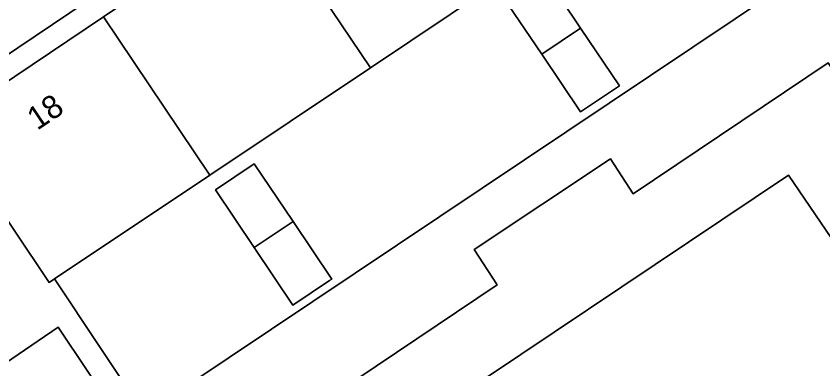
# Model space of a CAD drawing. Extents: x 158793 to 159888, y 384317 to 385256.
# Drawn here: x 159221.85 to 159256.79, y 384582.61 to 384597.87 of the extents above; entities that cross this region are included whole.
import ezdxf

# ---------------------------------------------------------------- set-up
doc = ezdxf.new("R2010")
doc.units = 0
for name, color, linetype in [('IMGEO_Erf', 7, 'Continuous'), ('IMGEO_Groenvoorziening', 7, 'Continuous'), ('IMGEO_Pand', 7, 'Continuous'), ('IMGEO_Pand_nummerreeks', 7, 'Continuous'), ('IMGEO_Rijbaan_lokaal_open', 7, 'Continuous'), ('IMGEO_Voetpad_gesloten', 7, 'Continuous'), ('IMGEO_Voetpad_open', 7, 'Continuous')]:
    doc.layers.add(name, color=color, linetype=linetype)

msp = doc.modelspace()

# ---------------------------------------------------------------- linework, layer by layer
at = {"layer": 'IMGEO_Erf'}
for points in [[(159253.972, 384600.287), (159250.947, 384604.835), (159244.149, 384600.292), (159237.191, 384595.643), (159230.234, 384590.995), (159223.505, 384586.498), (159227.4, 384580.648), (159254.824, 384599.006)], [(159242.935, 384598.725), (159244.619, 384599.858), (159246.296, 384597.36), (159247.98, 384594.851), (159246.292, 384593.732), (159244.614, 384596.228)], [(159233.84, 384588.989), (159235.516, 384586.495), (159235.426, 384586.435), (159233.833, 384585.363), (159232.157, 384587.857), (159230.48, 384590.351), (159232.164, 384591.483)]]:
    msp.add_lwpolyline(points, close=True, dxfattribs=at)
at = {"layer": 'IMGEO_Groenvoorziening'}
for points in [[(159245.073, 384674.375), (159284.084, 384616.156), (159275.927, 384610.681), (159273.311, 384614.477), (159265.419, 384609.219), (159264.866, 384609.954), (159259.381, 384606.275), (159260.51, 384604.607), (159254.969, 384600.946), (159255.845, 384599.623), (159254.824, 384599.006), (159227.4, 384580.648), (159223.505, 384586.498), (159223.273, 384586.343), (159218.681, 384593.177), (159217.583, 384592.512), (159220.423, 384588.255), (159209.629, 384581), (159206.819, 384585.213), (159203.401, 384582.912), (159198.891, 384579.876)], [(159242.691, 384586.237), (159241.692, 384587.769), (159247.59, 384591.694), (159248.575, 384590.183), (159257.026, 384595.85), (159264.913, 384583.752), (159277.399, 384592.138), (159286.257, 384578.984), (159286.133, 384578.901), (159294.892, 384565.894), (159262.678, 384544.258), (159259.822, 384548.509), (159259.697, 384548.426), (159257.475, 384546.941), (159253.387, 384544.208), (159252.964, 384543.926), (159252.893, 384543.878), (159259.749, 384533.873), (159262.59, 384535.774), (159262.993, 384535.164), (159312.028, 384567.885), (159313.543, 384565.466)], [(159208.686, 384574.19), (159223.666, 384584.415), (159228.726, 384576.872), (159242.691, 384586.237)]]:
    msp.add_lwpolyline(points, dxfattribs=at)
msp.add_lwpolyline([(159260.665, 384583.121), (159255.299, 384590.989), (159237.929, 384579.369), (159243.268, 384571.401)], close=True, dxfattribs=at)
at = {"layer": 'IMGEO_Pand'}
for points in [[(159239.509, 384607.189), (159232.566, 384602.519), (159237.191, 384595.643), (159244.149, 384600.292)], [(159232.566, 384602.519), (159225.624, 384597.848), (159230.234, 384590.995), (159237.191, 384595.643)], [(159242.935, 384598.725), (159244.614, 384596.228), (159246.296, 384597.36), (159244.619, 384599.858)], [(159225.624, 384597.848), (159218.681, 384593.177), (159223.273, 384586.343), (159223.505, 384586.498), (159230.234, 384590.995)], [(159246.296, 384597.36), (159244.614, 384596.228), (159246.292, 384593.732), (159247.98, 384594.851)], [(159230.48, 384590.351), (159232.157, 384587.857), (159233.84, 384588.989), (159232.164, 384591.483)], [(159233.84, 384588.989), (159232.157, 384587.857), (159233.833, 384585.363), (159235.426, 384586.435), (159235.516, 384586.495)]]:
    msp.add_lwpolyline(points, close=True, dxfattribs=at)
at = {"layer": 'IMGEO_Rijbaan_lokaal_open'}
msp.add_lwpolyline([(159218.146, 384593.974), (159245.904, 384612.649), (159243.491, 384616.357), (159239.864, 384613.935), (159238.633, 384613.113), (159230.662, 384607.789), (159229.312, 384606.888), (159229.548, 384606.535), (159226.662, 384604.556)], dxfattribs=at)
at = {"layer": 'IMGEO_Voetpad_gesloten'}
msp.add_lwpolyline([(159259, 384579.781), (159264.913, 384583.752), (159257.026, 384595.85), (159248.575, 384590.183), (159247.59, 384591.694), (159241.692, 384587.769), (159242.691, 384586.237), (159228.726, 384576.872), (159223.666, 384584.415), (159208.686, 384574.19)], dxfattribs=at)
msp.add_lwpolyline([(159255.299, 384590.989), (159260.665, 384583.121), (159243.268, 384571.401), (159237.929, 384579.369)], close=True, dxfattribs=at)
at = {"layer": 'IMGEO_Voetpad_open'}
msp.add_lwpolyline([(159239.509, 384607.189), (159246.451, 384611.86), (159245.904, 384612.649), (159218.146, 384593.974), (159218.681, 384593.177), (159225.624, 384597.848), (159232.566, 384602.519)], close=True, dxfattribs=at)

# ---------------------------------------------------------------- texts
at = {"layer": 'IMGEO_Pand_nummerreeks'}
msp.add_text('18', height=1, rotation=33.9306, dxfattribs=at).set_placement((159222.758, 384592.907))

doc.saveas('drawing.dxf')
